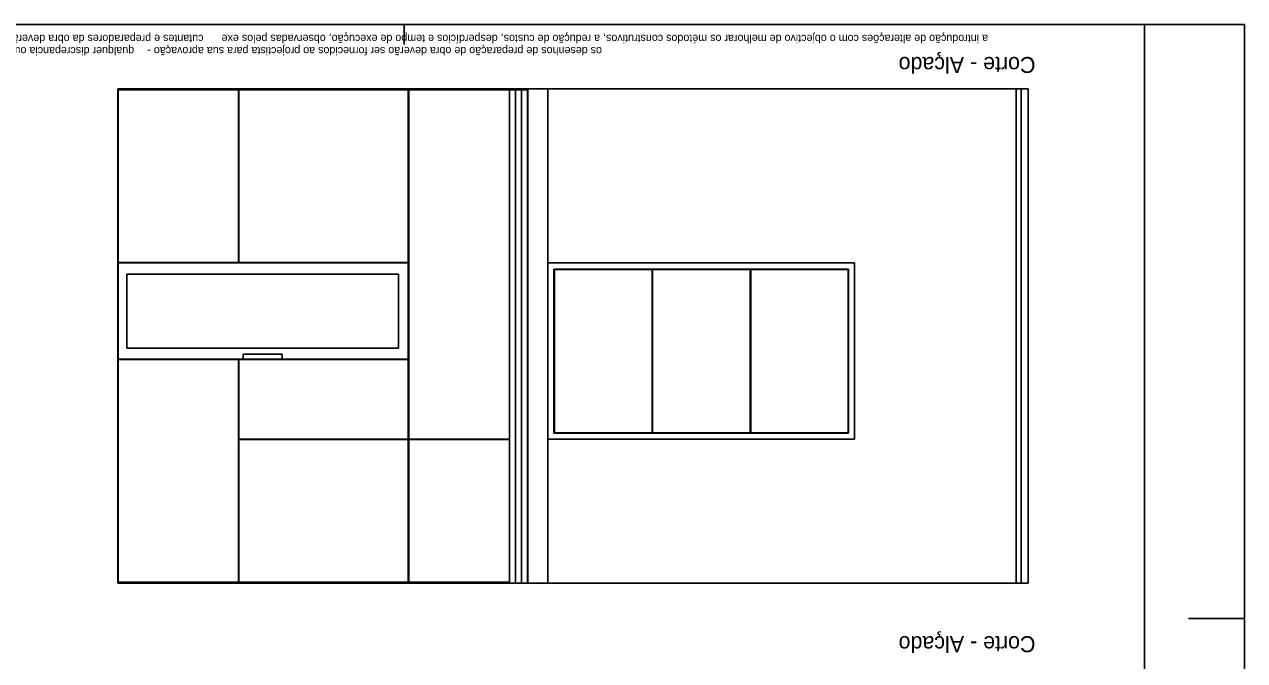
# Model space of a CAD drawing. Extents: x 1323.1 to 1334.7, y -308.5 to -300.1.
# Drawn here: x 1328.58 to 1334.67, y -303.32 to -300.14 of the extents above; entities that cross this region are included whole.
import ezdxf

# ---------------------------------------------------------------- set-up
doc = ezdxf.new("R2010")
doc.units = 0
for name, color, linetype in [('Level 1', 7, 'Continuous'), ('Level 13', 7, 'Continuous'), ('Level 2', 7, 'Continuous'), ('Level 60', 7, 'Continuous'), ('Level 62', 7, 'Continuous')]:
    doc.layers.add(name, color=color, linetype=linetype)

msp = doc.modelspace()

# ---------------------------------------------------------------- linework, layer by layer
at = {"layer": 'Level 1'}
for p, q in [((1333.5921, -300.46), (1329.0421, -300.46)), ((1329.0421, -300.46), (1329.0421, -302.93)), ((1333.5921, -302.93), (1329.0421, -302.93))]:
    msp.add_line(p, q, dxfattribs=at)
at = {"layer": 'Level 13'}
for p, q in [((1329.5141, -300.465), (1329.0421, -300.465)), ((1329.0441, -300.465), (1329.0441, -301.328)), ((1329.0441, -300.465), (1329.0441, -301.81)), ((1331.0001, -300.465), (1329.5161, -300.465)), ((1329.6461, -300.465), (1329.6461, -301.328)), ((1329.6481, -300.465), (1329.6481, -301.328)), ((1330.4941, -300.46), (1330.4941, -301.328)), ((1330.4961, -300.46), (1330.4961, -302.21)), ((1331.0001, -300.465), (1331.0901, -300.465)), ((1331.0001, -300.465), (1331.0001, -302.93)), ((1331.0301, -300.465), (1331.0301, -302.93)), ((1331.0601, -300.465), (1331.0601, -302.93)), ((1331.0901, -300.46), (1331.0901, -302.93)), ((1333.5571, -302.93), (1333.5571, -300.46)), ((1333.5921, -302.93), (1333.5921, -300.46)), ((1329.6461, -301.328), (1329.0441, -301.328)), ((1330.4941, -301.3299), (1329.0441, -301.3299)), ((1330.4941, -301.328), (1329.6481, -301.328)), ((1330.4941, -301.3299), (1330.4941, -301.81)), ((1331.1921, -301.3299), (1332.7241, -301.3299)), ((1331.1921, -301.3299), (1331.1921, -302.21)), ((1332.7241, -301.3299), (1332.7241, -302.21)), ((1330.4459, -301.385), (1329.0871, -301.385)), ((1329.0871, -301.385), (1329.0871, -301.755)), ((1330.4459, -301.385), (1330.4459, -301.755)), ((1331.2221, -301.36), (1332.6941, -301.36)), ((1331.2221, -301.36), (1331.2221, -302.18)), ((1332.6921, -301.362), (1331.2241, -301.362)), ((1331.2241, -301.362), (1331.2241, -302.178)), ((1331.7131, -302.178), (1331.7131, -301.362)), ((1331.7151, -302.178), (1331.7151, -301.362)), ((1332.2031, -302.178), (1332.2031, -301.362)), ((1332.2051, -302.178), (1332.2051, -301.362)), ((1332.6921, -301.362), (1332.6921, -302.18)), ((1332.6941, -301.36), (1332.6941, -302.18)), ((1330.4459, -301.755), (1329.0871, -301.755)), ((1330.4941, -301.81), (1329.0441, -301.81)), ((1329.0441, -301.812), (1329.0441, -302.925)), ((1329.6461, -301.812), (1329.0441, -301.812)), ((1329.6461, -301.812), (1329.6461, -302.925)), ((1329.6481, -301.81), (1329.8431, -301.81)), ((1330.4941, -301.812), (1329.6481, -301.812)), ((1329.6481, -301.812), (1329.6481, -302.21)), ((1329.669, -301.785), (1329.864, -301.785)), ((1329.669, -301.785), (1329.669, -301.81)), ((1329.864, -301.81), (1329.864, -301.785)), ((1330.4941, -301.812), (1330.4941, -302.21)), ((1331.2221, -302.18), (1332.6941, -302.18)), ((1331.2241, -302.178), (1332.6941, -302.178)), ((1330.4941, -302.21), (1329.6481, -302.21)), ((1329.6481, -302.212), (1329.6481, -302.925)), ((1330.1401, -302.212), (1329.6481, -302.212)), ((1330.4941, -302.212), (1330.1421, -302.212)), ((1330.4941, -302.212), (1330.4941, -302.925)), ((1331.0001, -302.21), (1330.4961, -302.21)), ((1330.4961, -302.212), (1330.4961, -302.925)), ((1331.0001, -302.212), (1330.4961, -302.212)), ((1331.1921, -302.21), (1332.7241, -302.21)), ((1329.6461, -302.925), (1329.0441, -302.925)), ((1330.4941, -302.925), (1329.6481, -302.925)), ((1331.0001, -302.925), (1330.4961, -302.925))]:
    msp.add_line(p, q, dxfattribs=at)
at = {"layer": 'Level 2'}
for p, q in [((1331.0921, -302.93), (1331.0921, -300.46)), ((1331.1921, -302.93), (1331.1921, -300.46)), ((1333.5321, -302.93), (1333.5321, -300.46))]:
    msp.add_line(p, q, dxfattribs=at)
at = {"layer": 'Level 62'}
for p, q in [((1330.4731, -300.2374), (1330.4731, -300.1374)), ((1334.1727, -308.5374), (1334.1727, -300.1374)), ((1334.6727, -303.1073), (1334.3927, -303.1073))]:
    msp.add_line(p, q, dxfattribs=at)
msp.add_lwpolyline([(1334.6727, -300.1374), (1334.6727, -308.5374), (1323.0731, -308.5374), (1323.0731, -300.1374)], close=True, dxfattribs=at)

# ---------------------------------------------------------------- texts
at = {"layer": 'Level 60'}
for p in [(1333.6278, -300.3), (1333.6278, -303.1951)]:
    msp.add_text('Corte - Alçado', height=0.08, rotation=180.00001, dxfattribs=at).set_placement(p)
at = {"layer": 'Level 62'}
for s, height, p in [('cutantes e preparadores da obra deverão ser sugeridas. não poderão no entanto ser implementadas sem o consentimento expresso dos responsáveis pela arquitectura', 0.0399996, (1329.4711, -300.1894)), ('a introdução de alterações com o objectivo de melhorar os métodos construtivos, a redução de custos, desperdícios e tempo de execução, observadas pelos exe', 0.0399996, (1333.3909, -300.1894)), ('qualquer discrepancia ou incoerencia detectada deverá ser comunicada aos responsáveis pela arquitectura com o objectivo de ser analizada e corrigida -', 0.0399996, (1329.1245, -300.2504)), ('os desenhos de preparação de obra deverão ser fornecidos ao projectista para sua aprovação -', 0.04, (1331.4619, -300.2504))]:
    msp.add_text(s, height=height, rotation=180, dxfattribs=at).set_placement(p)

doc.saveas('drawing.dxf')
